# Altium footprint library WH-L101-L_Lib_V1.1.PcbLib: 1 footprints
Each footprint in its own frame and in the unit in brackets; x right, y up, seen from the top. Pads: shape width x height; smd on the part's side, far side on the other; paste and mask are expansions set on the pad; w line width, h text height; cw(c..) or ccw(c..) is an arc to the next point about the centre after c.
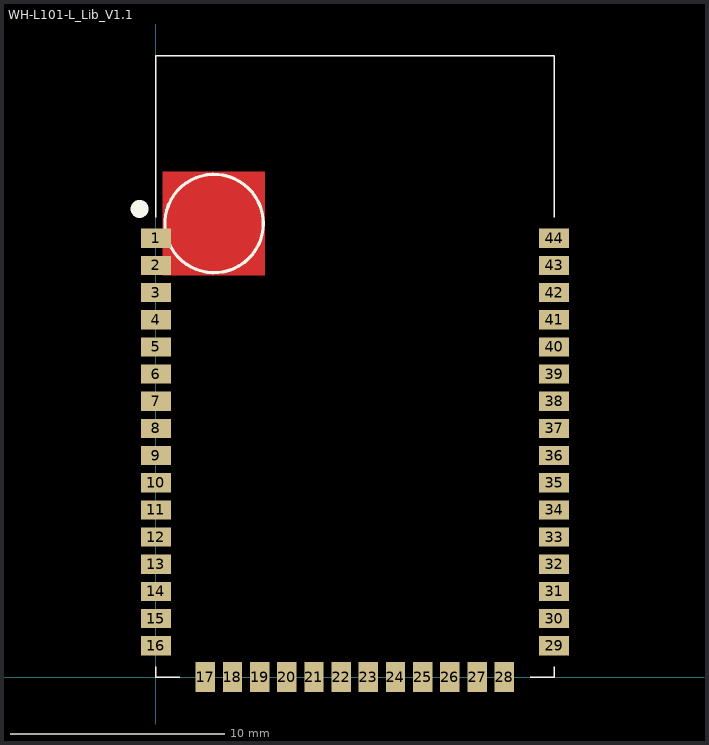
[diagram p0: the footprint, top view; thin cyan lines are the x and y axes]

## WH-L101-L_Lib_V1.1 [mm] "WH-L101封装"
pads (44):
  rect 1.4x0.9 smd: 1(0,20.52) 2(0,19.25) 3(0,17.98) 4(0,16.71) 5(0,15.44) 6(0,14.17) 7(0,12.9) 8(0,11.63) 9(0,10.36) 10(0,9.09) 11(0,7.82) 12(0,6.55) 13(0,5.28) 14(0,4.01) 15(0,2.74) 16(0,1.47) 29(18.62,1.47) 30(18.62,2.74) 31(18.62,4.01) 32(18.62,5.28) 33(18.62,6.55) 34(18.62,7.82) 35(18.62,9.09) 36(18.62,10.36) 37(18.62,11.63) 38(18.62,12.9) 39(18.62,14.17) 40(18.62,15.44) 41(18.62,16.71) 42(18.62,17.98) 43(18.62,19.25) 44(18.62,20.52)
  rect 0.9x1.4 smd: 17(2.31,0) 18(3.58,0) 19(4.85,0) 20(6.12,0) 21(7.39,0) 22(8.66,0) 23(9.93,0) 24(11.2,0) 25(12.47,0) 26(13.74,0) 27(15.02,0) 28(16.29,0)
Top Layer:
  pour cut-out: 0.33,23.622 5.08,23.622 5.08,18.796 0.33,18.796
Top Overlay:
  circle w0.762: c-0.762,21.895 r0.036
  circle w0.152: c2.72,21.21 r2.3
  lines w0.07: 0,0.5 0,0 1.12,0 ; 0,21.5 0,29.05 18.62,29.05 18.62,21.5 ; 17.5,0 18.62,0 18.62,0.5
